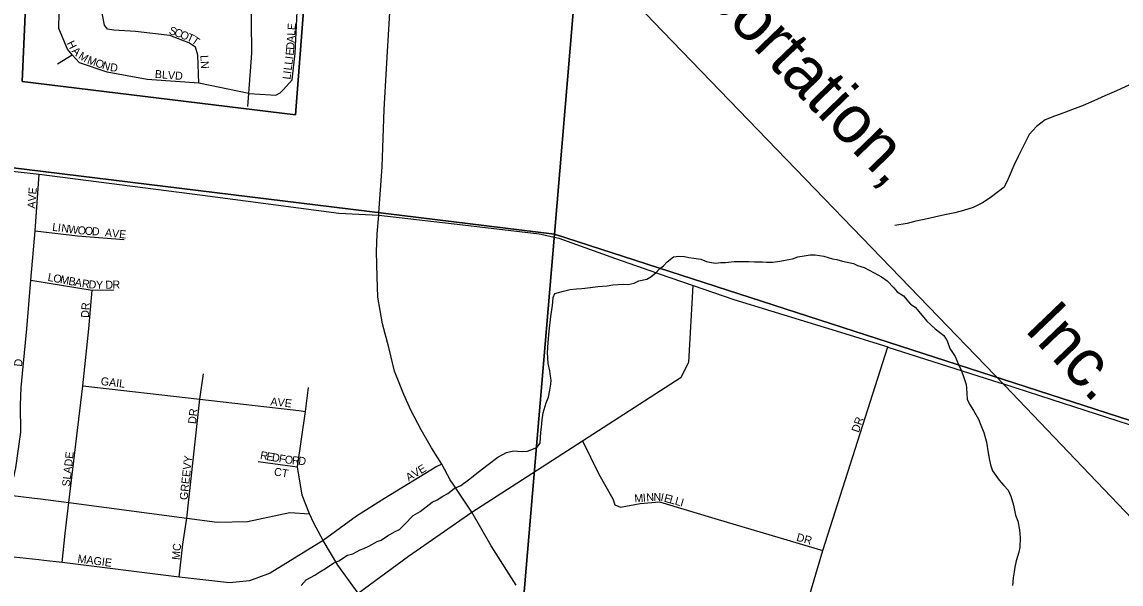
# Model space of a CAD drawing. Extents: x 1310247 to 1552180, y 377264 to 706493.
# Drawn here: x 1388764 to 1395630, y 496435 to 499946 of the extents above; entities that cross this region are included whole.
import ezdxf

# ---------------------------------------------------------------- set-up
doc = ezdxf.new("R2010")
doc.units = 0
for name, color, linetype in [('GM_X_City_Street', 7, 'Continuous'), ('GM_X_City_Street_Text', 7, 'Continuous'), ('GM_X_Corporation', 7, 'Continuous'), ('GM_X_Minor_River', 7, 'Continuous'), ('GM_X_Rail_Line', 7, 'Continuous'), ('GM_X_Rail_Line_Text', 7, 'Continuous'), ('GM_X_Section', 7, 'Continuous'), ('GM_X_State_Route', 7, 'Continuous')]:
    doc.layers.add(name, color=color, linetype=linetype)

msp = doc.modelspace()

# ---------------------------------------------------------------- linework, layer by layer
at = {"layer": 'GM_X_City_Street'}
for points in [[(1390180.6, 499499), (1389869.4, 499562.9), (1389545.8, 499587.2), (1389296.7, 499632.1), (1389123.8, 499691.7), (1389078.3, 499741.6), (1389047.5, 499775.4), (1388994, 499904.9), (1389000, 500207.8), (1389012.1, 500416.4), (1389034.7, 500546.4), (1389166.4, 500734.5), (1389178.2, 500824.6), (1389252.4, 501443.4)], [(1390174.6, 499418.6), (1390180.6, 499499), (1390199.2, 499751.3), (1390198, 499952.1), (1390197.8, 499986.1), (1390194.5, 500120.7), (1390181.1, 500251.4), (1390106.9, 500426.5), (1390096.6, 500632.3), (1390115.9, 500754.9)], [(1390180.6, 499499), (1390318.1, 499490), (1390350.7, 499489.1), (1390376.3, 499503), (1390397.8, 499524.7), (1390452.5, 499585.5), (1390469.7, 499752.1), (1390502.7, 500401), (1390489.5, 500486.9), (1390417.2, 500557.9), (1390378.4, 500583.2), (1390335.8, 500591.6), (1390096.6, 500632.3)], [(1389869.4, 499562.9), (1389862.9, 499739.7), (1389848.8, 499788.4), (1389806.4, 499815), (1389687.3, 499861.4), (1389473.8, 499887.6), (1389337.8, 499894.3), (1389297.5, 499901), (1389278.5, 499925.5), (1389264, 500002.1), (1389267.6, 500082.3), (1389270.7, 500173.1)], [(1388985.6, 499684.3), (1389078.3, 499741.6)], [(1388422.5, 499043.6), (1388433.8, 499042.1), (1388665.3, 499017.6), (1388870.7, 498996.3), (1389890.6, 498863.2)], [(1388771.1, 497793.5), (1388794.1, 498029.9), (1388819, 498333.5), (1388845.5, 498642.3), (1388870.7, 498996.3)], [(1389890.6, 498863.2), (1390350, 498803.3), (1390743.6, 498752.5), (1390992.6, 498738.6)], [(1390992.6, 498738.6), (1391517.3, 498679.7), (1391994.4, 498621.9), (1392117.7, 498594.7), (1392471.6, 498467.6), (1392727.3, 498379.3)], [(1388845.5, 498642.3), (1389110.9, 498609.1), (1389402.7, 498586.2)], [(1392727.3, 498379.3), (1392744.7, 498373.3), (1392957.6, 498299.8), (1393211.5, 498212.1), (1393905, 498000.7), (1394171.8, 497915.6), (1394173.8, 497914.9)], [(1388819, 498333.5), (1389201.9, 498269.7), (1389336.7, 498272.5)], [(1388858.2, 493882), (1388874.8, 494185.3), (1388875, 494301.6), (1388891.1, 494407.6), (1388908.9, 494503.6), (1388946.5, 494589.1), (1389061.3, 494733.4), (1389401.1, 495032), (1389702.7, 495292.1), (1389943.2, 495528.3), (1390307.7, 495891.8), (1390864.8, 496378.4), (1391178.7, 496608.5), (1391573.3, 496882.9), (1392264.6, 497329.3), (1392881.4, 497727.5), (1392929.2, 497820.9), (1392957.6, 498299.8)], [(1389015.7, 496569.1), (1389034.1, 496750.2), (1389056.9, 496943.9), (1389143.8, 497673.2), (1389181, 498030), (1389201.9, 498269.7)], [(1393484.5, 495686.5), (1393767, 496644.1), (1394171.8, 497915.6)], [(1394173.8, 497914.9), (1394872.5, 497691.8)], [(1388635.7, 496649.9), (1388636.1, 496653.9), (1388638.1, 496674.8), (1388687.8, 496990.6), (1388724.6, 497161.6), (1388755.8, 497382.9), (1388755.4, 497552.7), (1388758.5, 497663.3), (1388771.1, 497793.5)], [(1389745.4, 496476.5), (1389768.3, 496683.5), (1389792.8, 496846.3), (1389875.3, 497589.7), (1389897.9, 497747.1)], [(1394872.5, 497691.8), (1394888.5, 497686.7), (1395198.1, 497587.8), (1396433.6, 497187.4), (1397215.8, 496934.8)], [(1389143.8, 497673.2), (1389875.3, 497589.7), (1390494.3, 497519), (1390534, 497512.4)], [(1391818.9, 495654.5), (1391475.3, 495749.8), (1391229.8, 495884.7), (1391093.9, 496007.1), (1390990.7, 496173.9), (1390864.8, 496378.4), (1390736.3, 496553.2), (1390644.8, 496707.3), (1390586.1, 496815.5), (1390559.3, 496872.4), (1390515, 496989.3), (1390484.1, 497166.6), (1390534, 497512.4), (1390552.9, 497662.5)], [(1392264.6, 497329.3), (1392367.7, 497121.3), (1392454.8, 496967.2), (1392468.2, 496929), (1392503.8, 496914.2), (1392626.3, 496938), (1392746.5, 496947.8), (1393112.5, 496838.7), (1393767, 496644.1)], [(1391386.1, 497182.8), (1391356.2, 497169.9), (1391029, 496968), (1390853.6, 496857.8), (1390644.8, 496707.3), (1390314.3, 496502.6), (1390185, 496454.3), (1390060.9, 496441.6), (1389745.4, 496476.5), (1389015.7, 496569.1), (1388899.4, 496581.6)], [(1390240, 497201.1), (1390421.8, 497175.8), (1390484.1, 497166.6)], [(1387563.5, 497127.5), (1388687.8, 496990.6), (1388842.8, 496971.1), (1388879, 496966.5)], [(1388879, 496966.5), (1389056.9, 496943.9), (1389792.8, 496846.3), (1389984, 496820.2), (1390173.4, 496825), (1390437.6, 496881.8), (1390559.3, 496872.4)], [(1388899.4, 496581.6), (1388868.4, 496584.9), (1388631.9, 496610.5), (1387545.8, 496727.6), (1387080.9, 496769.3), (1387050, 496772.1), (1386156.4, 496848.2)]]:
    msp.add_lwpolyline(points, dxfattribs=at)
at = {"layer": 'GM_X_Corporation'}
for points in [[(1388825.5, 500926.9), (1388764.4, 499574.1), (1390471.8, 499365.5), (1390574.6, 500695.1)], [(1390574.6, 500695.1), (1390471.8, 499365.5), (1388764.4, 499574.1), (1388825.5, 500926.9)]]:
    msp.add_lwpolyline(points, dxfattribs=at)
at = {"layer": 'GM_X_Minor_River'}
for points in [[(1395677.4, 499550.9), (1395602.2, 499516.8), (1395529.1, 499484.6), (1395460, 499454.3), (1395393, 499424), (1395326.1, 499399.7), (1395271.3, 499379), (1395214.6, 499358.5), (1395155.7, 499334), (1395102.4, 499293.2), (1395054.8, 499242.2), (1395018.7, 499168.9), (1394986.9, 499105.4), (1394959.2, 499049.9), (1394924.8, 498966.5), (1394899.3, 498914.9), (1394821.4, 498854.7), (1394768.2, 498818), (1394705.2, 498787.5), (1394644.5, 498769.1), (1394591.9, 498754.4), (1394529.3, 498742), (1394464.7, 498725.7), (1394400, 498711.4), (1394347.6, 498700.7), (1394293, 498688.1), (1394216.4, 498674.1)], [(1390508.2, 496424.8), (1390539.2, 496460.1), (1390592.3, 496490.9), (1390624.9, 496510.1), (1390659.6, 496531.3), (1390712.8, 496568.1), (1390743.2, 496579.4), (1390798.4, 496614.1), (1390830.8, 496623.4), (1390875.6, 496648.3), (1390899.9, 496655.7), (1390930.5, 496671), (1390983.4, 496699.8), (1391007.8, 496709.2), (1391046.7, 496736.3), (1391095.6, 496763.2), (1391122, 496774.5), (1391153, 496805.9), (1391206.7, 496862.8), (1391251.6, 496887.7), (1391325.4, 496946.1), (1391358, 496961.3), (1391392.7, 496984.5), (1391423.2, 496999.8), (1391464.2, 497030.9), (1391504.9, 497049.9), (1391554.1, 497084.8), (1391613.6, 497133.5), (1391677.1, 497182.1), (1391736.6, 497226.8), (1391791.6, 497255.5), (1391834, 497266.5), (1391862.1, 497265.7), (1391890.2, 497263), (1391922.4, 497264.2), (1391979.2, 497286.8), (1392000, 497314.4), (1392005.8, 497382.5), (1392008.7, 497414.6), (1392013.9, 497460.7), (1392019.1, 497504.7), (1392038.8, 497566.5), (1392053.8, 497602.3), (1392061, 497646.3), (1392068, 497682.3), (1392068.7, 497708.4), (1392065.3, 497732.5), (1392062.2, 497766.8), (1392051.4, 497813.3), (1392048.3, 497847.5), (1392047.1, 497879.7), (1392050.8, 497943.8), (1392056.7, 498014), (1392067.1, 498106.1), (1392079, 498174.1), (1392079.6, 498198.2), (1392082.3, 498224.3), (1392093, 498250.1), (1392147.7, 498264.8), (1392188.1, 498273.8), (1392228.4, 498278.8), (1392260.6, 498281.9), (1392315, 498286.6), (1392361.4, 498293.4), (1392419.7, 498297.9), (1392454, 498303.1), (1392488.2, 498306.2), (1392520.4, 498307.4), (1392550.5, 498306.6), (1392588.9, 498313.7), (1392617.4, 498329), (1392667.9, 498339.8), (1392692.4, 498353.2), (1392725.2, 498380.5), (1392745.9, 498404), (1392770.5, 498423.5), (1392795.3, 498447), (1392834.3, 498478.1), (1392866.5, 498483.3), (1392902.6, 498480.3), (1392930.6, 498475.6), (1392960.6, 498470.8), (1393004.6, 498463.6), (1393040.4, 498448.7), (1393070.4, 498443.9), (1393096.4, 498439.2)], [(1393096.4, 498439.2), (1393128.6, 498442.4), (1393158.7, 498443.6), (1393213.2, 498450.2), (1393241.3, 498449.5), (1393273.4, 498450.7), (1393303.5, 498449.9), (1393339.6, 498447), (1393389.9, 498447.7), (1393415.9, 498445), (1393454.1, 498446), (1393498.4, 498450.9), (1393530.7, 498458.1), (1393577.2, 498467), (1393611.6, 498478.1), (1393650, 498485.2), (1393688.3, 498492.2), (1393718.4, 498491.5), (1393772.4, 498482), (1393828.2, 498466.5), (1393854.2, 498461.8), (1393890.1, 498450.9), (1393958, 498437.1), (1393983.8, 498424.3), (1394025.6, 498411.2), (1394087.1, 498379.5), (1394132.6, 498354.2), (1394168.1, 498329.2), (1394211.1, 498285.9), (1394230.5, 498259.3), (1394270, 498234.2), (1394314.9, 498182.8), (1394344.5, 498164), (1394377.6, 498125), (1394416.5, 498077.7), (1394469.5, 498028.2), (1394522.6, 497986.6), (1394543.8, 497953.9), (1394560.6, 497905.3), (1394593.5, 497856.2), (1394614.2, 497805.5), (1394633.3, 497766.8), (1394650.1, 497718.2), (1394661.2, 497681.7), (1394664.5, 497657.5), (1394665.6, 497623.4), (1394668.8, 497589.1), (1394682, 497558.7), (1394707, 497517.8), (1394739.8, 497464.8), (1394752.8, 497426.3), (1394771.7, 497381.6), (1394788.2, 497320.9), (1394800.5, 497254.3), (1394807.3, 497207.9), (1394814.6, 497179.6), (1394827.7, 497141.1), (1394847, 497112.5), (1394868.3, 497083.8), (1394897.6, 497050.9), (1394924.9, 497020.1), (1394942, 496983.5), (1394958.6, 496926.8), (1394971, 496864.2), (1394984.1, 496827.7), (1394994.7, 496773.2), (1394999.4, 496724.9), (1394997.8, 496662.7), (1394991, 496634.7), (1394973.5, 496578.9), (1394966.4, 496540.9), (1394961.6, 496510.9), (1394956.6, 496472.9), (1394951.3, 496424.8)]]:
    msp.add_lwpolyline(points, dxfattribs=at)
at = {"layer": 'GM_X_Rail_Line'}
msp.add_lwpolyline([(1391215.5, 501528.6), (1391363.1, 501366.3), (1391669.4, 501041.6), (1392708.6, 499946.2), (1394901.9, 497676.2), (1397119, 495354.7), (1398298.2, 494121.8), (1399986, 492365.7), (1401928, 490322.8), (1402792, 489425.8), (1403343.8, 488836.2), (1404387.5, 487753.6), (1405733.2, 486333.5), (1406735.3, 485281.4), (1408853, 483062.5), (1411288.7, 480519.4)], dxfattribs=at)
at = {"layer": 'GM_X_Section'}
for points in [[(1386797.9, 504663.1), (1392551, 504087.3), (1392089.7, 498619.6), (1386361.6, 499322.8)], [(1392551, 504087.3), (1397709.1, 501901.1), (1397269.5, 496943), (1392089.7, 498619.6)], [(1386361.6, 499322.8), (1392089.7, 498619.6), (1391637.2, 493267.7), (1385887.9, 493921.2)], [(1392089.7, 498619.6), (1397269.5, 496943), (1396822, 491632.9), (1391637.2, 493267.7)]]:
    msp.add_lwpolyline(points, close=True, dxfattribs=at)
at = {"layer": 'GM_X_State_Route'}
for points in [[(1390993.7, 498754.6), (1391014.5, 499041), (1391025.8, 499400), (1391047, 499761.2), (1391063.9, 500039.1), (1391089.3, 500376.2), (1391103.4, 500589.3), (1391110, 500655.1)], [(1391456.6, 497059.4), (1391439.1, 497085.8), (1391386.1, 497182.8), (1391322, 497285.3), (1391257.9, 497398.8), (1391192.1, 497521.4), (1391150, 497618.5), (1391091.4, 497764.9), (1391056.6, 497913.1), (1391016.3, 498059.6), (1390987, 498226.1), (1390983.4, 498354.3), (1390977.9, 498509.8), (1390983.4, 498623.3), (1390992.6, 498738.6), (1390993.7, 498754.6)], [(1391851.9, 496427.8), (1391694.5, 496674), (1391573.3, 496882.9), (1391456.6, 497059.4)]]:
    msp.add_lwpolyline(points, dxfattribs=at)

# ---------------------------------------------------------------- texts
at = {"layer": 'GM_X_City_Street_Text'}
for s, rotation, p in [('S', 339.43916, (1389677.7, 499874)), ('C', 339.45643, (1389710.7, 499861.6)), ('O', 339.45291, (1389747.8, 499847.7)), ('L', 86.10829, (1390469.8, 499859.1)), ('E', 86.09051, (1390472.1, 499894.2)), ('H', 296.7752, (1389042.2, 499814.1)), ('T', 335.77537, (1389788.2, 499832.6)), ('T', 325.62796, (1389818.2, 499819.3)), ('D', 86.01817, (1390463.7, 499771.2)), ('A', 86.09691, (1390466.8, 499815.1)), ('A', 313.9959, (1389071.5, 499761.5)), ('M', 327.58027, (1389112, 499721.7)), ('E', 84.3057, (1390460.1, 499734.5)), ('M', 340.45149, (1389167.6, 499688)), ('O', 340.3969, (1389217.4, 499670.3)), ('N', 342.91151, (1389261.1, 499654.8)), ('D', 352.00437, (1389311.6, 499640)), ('LN', 273.01128, (1389878.2, 499737.8)), ('L', 82.53442, (1390452.5, 499676.1)), ('I', 82.54108, (1390457, 499711.1)), ('BLVD', 355.48541, (1389592.3, 499597.1)), ('L', 82.53442, (1390440.5, 499584.5)), ('I', 82.54108, (1390445, 499619.4)), ('L', 82.53442, (1390447.9, 499641.2)), ('AVE', 86.05312, (1388847.4, 498778.8)), ('L', 352.34127, (1388950.5, 498642.2)), ('I', 352.33336, (1388985.3, 498637.5)), ('N', 352.33819, (1389007.1, 498634.6)), ('W', 352.63155, (1389051, 498628.7)), ('O', 355.35315, (1389110.3, 498621.1)), ('O', 356.17567, (1389155, 498617.5)), ('D', 356.18302, (1389198.9, 498614.5)), ('AVE', 353.88395, (1389280.2, 498607.1)), ('L', 349.37962, (1388921.7, 498329.5)), ('O', 349.37962, (1388956.3, 498323)), ('M', 349.37962, (1388999.5, 498314.9)), ('B', 349.37962, (1389051.4, 498305.1)), ('A', 349.37962, (1389090.4, 498297.8)), ('R', 351.38286, (1389135.5, 498289.4)), ('D', 355.38934, (1389178.4, 498283)), ('Y', 359.39583, (1389226.1, 498279.3)), ('D', 1.39907, (1389285.2, 498279.2)), ('R', 1.39907, (1389329.2, 498280.3)), ('DR', 86.98328, (1389181.8, 498096.6)), ('D', 84.14072, (1388763.5, 497791.2)), ('GAIL', 353.08947, (1389253.9, 497678.7)), ('AVE', 354.09322, (1390314.2, 497551.1)), ('DR', 83.98829, (1389850.7, 497432.7)), ('DR', 71.56323, (1393991.5, 497377.5)), ('SLADE', 83.66087, (1389063.1, 497041.2)), ('GREEVY', 83.88607, (1389797.8, 496957.5)), ('R', 350.11651, (1390248.8, 497216.6)), ('E', 350.11547, (1390287.8, 497209.8)), ('D', 350.11547, (1390322.5, 497203.7)), ('F', 350.11547, (1390365.9, 497196.2)), ('O', 352.70054, (1390403, 497189.8)), ('R', 355.34772, (1390449.1, 497183.9)), ('D', 355.42651, (1390488.7, 497180.7)), ('CT', 349.99129, (1390335.1, 497114.3)), ('AVE', 30.96311, (1391179.6, 497074.6)), ('N', 4.71831, (1392666.1, 496949.8)), ('N', 0.60102, (1392709, 496953.4)), ('I', 349.00302, (1392750.4, 496954.1)), ('M', 4.7228, (1392591.6, 496943.7)), ('I', 4.71932, (1392644.2, 496948)), ('E', 344.93659, (1392771, 496950.1)), ('L', 344.48247, (1392804.9, 496941)), ('L', 344.46931, (1392838.8, 496931.6)), ('I', 344.49244, (1392872.8, 496922.2)), ('DR', 344.47808, (1393598.1, 496705.8)), ('MC', 84.80332, (1389749.4, 496583.4)), ('MAGIE', 352.56788, (1389108.8, 496569.8))]:
    msp.add_text(s, height=50, rotation=rotation, dxfattribs=at).set_placement(p)
at = {"layer": 'GM_X_Rail_Line_Text'}
for s, rotation, p in [('Transportation,', 313.9502, (1392305, 500842.4)), ('Inc.', 313.81536, (1395018.8, 498022.5))]:
    msp.add_text(s, height=299, rotation=rotation, dxfattribs=at).set_placement(p)

doc.saveas('drawing.dxf')
